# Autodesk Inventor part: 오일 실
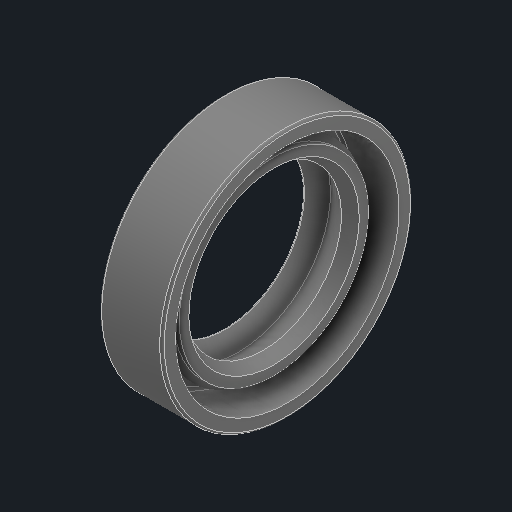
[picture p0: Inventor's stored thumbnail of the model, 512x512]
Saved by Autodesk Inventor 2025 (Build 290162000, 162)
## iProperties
Created: 2025-08
Part Number: 오일 실
Material: 고무
Description: 오일-실
Document SubType Name: Modeling
Designer: infra023
Density: 0.93 g/cm^3
Appearance: 기본값
Author: jhkim
Sending System: Autodesk Inventor 2026
Preprocessor: ST-DEVELOPER v20.1
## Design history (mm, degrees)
feature "Solid1"
node "솔리드1"
